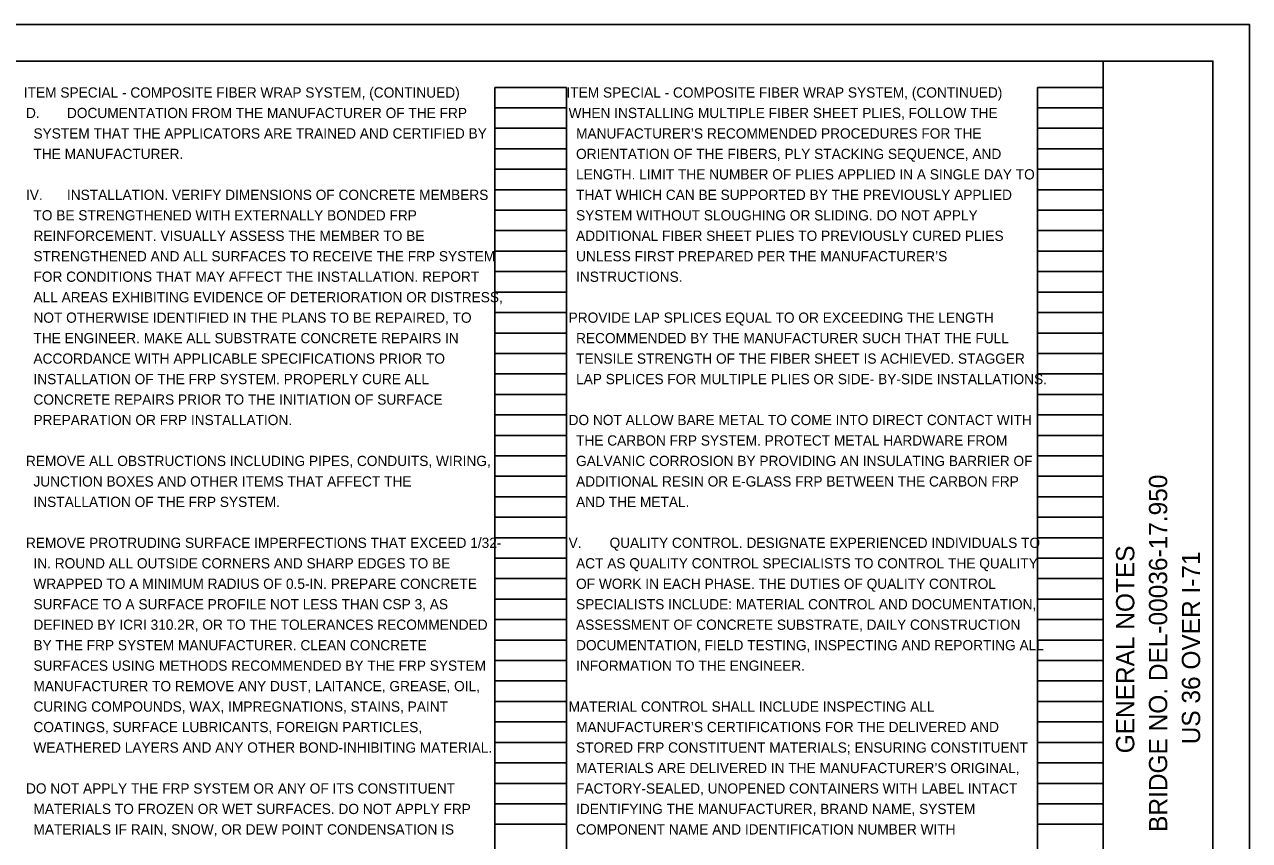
# Model space of a CAD drawing. Extents: x 0 to 90.2, y -3.7 to 22.
# Drawn here: x 17.25 to 34, y 10.84 to 22 of the extents above; entities that cross this region are included whole.
import ezdxf

# ---------------------------------------------------------------- set-up
doc = ezdxf.new("R2010")
doc.units = 0
for name, color, linetype in [('Default', 7, 'Continuous'), ('SH_Border', 7, 'Continuous'), ('SH_Cut_Line', 7, 'Continuous'), ('SH_Data', 7, 'Continuous'), ('SH_Text', 7, 'Continuous')]:
    doc.layers.add(name, color=color, linetype=linetype)

msp = doc.modelspace()

# ---------------------------------------------------------------- linework, layer by layer
at = {"layer": 'SH_Border'}
msp.add_line((32, 0.5), (32, 21.5), dxfattribs=at)
msp.add_lwpolyline([(1.5, 21.5), (33.5, 21.5), (33.5, 0.5), (1.5, 0.5)], close=True, dxfattribs=at)
at = {"layer": 'SH_Cut_Line'}
msp.add_lwpolyline([(0, 0), (34, 0), (34, 22), (0, 22)], close=True, dxfattribs=at)
at = {"layer": 'SH_Data'}
for p, q in [((23.68, 0.98), (23.68, 21.14)), ((23.68, 21.14), (24.66, 21.14)), ((24.66, 0.98), (24.66, 21.14)), ((31.1, 0.98), (31.1, 21.14)), ((31.1, 21.14), (32, 21.14)), ((32, 0.98), (32, 21.14)), ((23.68, 20.86), (24.66, 20.86)), ((31.1, 20.86), (32, 20.86)), ((23.68, 20.58), (24.66, 20.58)), ((31.1, 20.58), (32, 20.58)), ((23.68, 20.3), (24.66, 20.3)), ((31.1, 20.3), (32, 20.3)), ((23.68, 20.02), (24.66, 20.02)), ((31.1, 20.02), (32, 20.02)), ((23.68, 19.74), (24.66, 19.74)), ((31.1, 19.74), (32, 19.74)), ((23.68, 19.46), (24.66, 19.46)), ((31.1, 19.46), (32, 19.46)), ((23.68, 19.18), (24.66, 19.18)), ((31.1, 19.18), (32, 19.18)), ((23.68, 18.9), (24.66, 18.9)), ((31.1, 18.9), (32, 18.9)), ((23.68, 18.62), (24.66, 18.62)), ((31.1, 18.62), (32, 18.62)), ((23.68, 18.34), (24.66, 18.34)), ((31.1, 18.34), (32, 18.34)), ((23.68, 18.06), (24.66, 18.06)), ((31.1, 18.06), (32, 18.06)), ((23.68, 17.78), (24.66, 17.78)), ((31.1, 17.78), (32, 17.78)), ((23.68, 17.5), (24.66, 17.5)), ((31.1, 17.5), (32, 17.5)), ((23.68, 17.22), (24.66, 17.22)), ((31.1, 17.22), (32, 17.22)), ((23.68, 16.94), (24.66, 16.94)), ((31.1, 16.94), (32, 16.94)), ((23.68, 16.66), (24.66, 16.66)), ((31.1, 16.66), (32, 16.66)), ((23.68, 16.38), (24.66, 16.38)), ((31.1, 16.38), (32, 16.38)), ((23.68, 16.1), (24.66, 16.1)), ((31.1, 16.1), (32, 16.1)), ((23.68, 15.82), (24.66, 15.82)), ((31.1, 15.82), (32, 15.82)), ((23.68, 15.54), (24.66, 15.54)), ((31.1, 15.54), (32, 15.54)), ((23.68, 15.26), (24.66, 15.26)), ((31.1, 15.26), (32, 15.26)), ((23.68, 14.98), (24.66, 14.98)), ((31.1, 14.98), (32, 14.98)), ((23.68, 14.7), (24.66, 14.7)), ((31.1, 14.7), (32, 14.7)), ((23.68, 14.42), (24.66, 14.42)), ((31.1, 14.42), (32, 14.42)), ((23.68, 14.14), (24.66, 14.14)), ((31.1, 14.14), (32, 14.14)), ((23.68, 13.86), (24.66, 13.86)), ((31.1, 13.86), (32, 13.86)), ((23.68, 13.58), (24.66, 13.58)), ((31.1, 13.58), (32, 13.58)), ((23.68, 13.3), (24.66, 13.3)), ((31.1, 13.3), (32, 13.3)), ((23.68, 13.02), (24.66, 13.02)), ((31.1, 13.02), (32, 13.02)), ((23.68, 12.74), (24.66, 12.74)), ((31.1, 12.74), (32, 12.74)), ((23.68, 12.46), (24.66, 12.46)), ((31.1, 12.46), (32, 12.46)), ((23.68, 12.18), (24.66, 12.18)), ((31.1, 12.18), (32, 12.18)), ((23.68, 11.9), (24.66, 11.9)), ((31.1, 11.9), (32, 11.9)), ((23.68, 11.62), (24.66, 11.62)), ((31.1, 11.62), (32, 11.62)), ((23.68, 11.34), (24.66, 11.34)), ((31.1, 11.34), (32, 11.34)), ((23.68, 11.06), (24.66, 11.06)), ((31.1, 11.06), (32, 11.06))]:
    msp.add_line(p, q, dxfattribs=at)

# ---------------------------------------------------------------- texts
at = {"layer": 'Default'}
for s, p in [('D.', (17.269, 20.72)), ('DOCUMENTATION FROM THE MANUFACTURER OF THE FRP ', (17.829, 20.72)), ('WHEN INSTALLING MULTIPLE FIBER SHEET PLIES, FOLLOW THE ', (24.689, 20.72)), ('SYSTEM THAT THE APPLICATORS ARE TRAINED AND CERTIFIED BY ', (17.371, 20.44)), ('MANUFACTURER’S RECOMMENDED PROCEDURES FOR THE ', (24.791, 20.44)), ('THE MANUFACTURER.', (17.371, 20.16)), ('ORIENTATION OF THE FIBERS, PLY STACKING SEQUENCE, AND ', (24.791, 20.16)), ('LENGTH. LIMIT THE NUMBER OF PLIES APPLIED IN A SINGLE DAY TO ', (24.791, 19.88)), ('IV.', (17.269, 19.6)), ('INSTALLATION. VERIFY DIMENSIONS OF CONCRETE MEMBERS ', (17.829, 19.6)), ('THAT WHICH CAN BE SUPPORTED BY THE PREVIOUSLY APPLIED ', (24.791, 19.6)), ('TO BE STRENGTHENED WITH EXTERNALLY BONDED FRP ', (17.371, 19.32)), ('SYSTEM WITHOUT SLOUGHING OR SLIDING. DO NOT APPLY ', (24.791, 19.32)), ('REINFORCEMENT. VISUALLY ASSESS THE MEMBER TO BE ', (17.371, 19.04)), ('ADDITIONAL FIBER SHEET PLIES TO PREVIOUSLY CURED PLIES ', (24.791, 19.04)), ('STRENGTHENED AND ALL SURFACES TO RECEIVE THE FRP SYSTEM ', (17.371, 18.76)), ('UNLESS FIRST PREPARED PER THE MANUFACTURER’S ', (24.791, 18.76)), ('FOR CONDITIONS THAT MAY AFFECT THE INSTALLATION. REPORT ', (17.371, 18.48)), ('INSTRUCTIONS.', (24.791, 18.48)), ('ALL AREAS EXHIBITING EVIDENCE OF DETERIORATION OR DISTRESS, ', (17.371, 18.2)), ('NOT OTHERWISE IDENTIFIED IN THE PLANS TO BE REPAIRED, TO ', (17.371, 17.92)), ('PROVIDE LAP SPLICES EQUAL TO OR EXCEEDING THE LENGTH ', (24.689, 17.92)), ('THE ENGINEER. MAKE ALL SUBSTRATE CONCRETE REPAIRS IN ', (17.371, 17.64)), ('RECOMMENDED BY THE MANUFACTURER SUCH THAT THE FULL ', (24.791, 17.64)), ('ACCORDANCE WITH APPLICABLE SPECIFICATIONS PRIOR TO ', (17.371, 17.36)), ('TENSILE STRENGTH OF THE FIBER SHEET IS ACHIEVED. STAGGER ', (24.791, 17.36)), ('INSTALLATION OF THE FRP SYSTEM. PROPERLY CURE ALL ', (17.371, 17.08)), ('LAP SPLICES FOR MULTIPLE PLIES OR SIDE- BY-SIDE INSTALLATIONS.', (24.791, 17.08)), ('CONCRETE REPAIRS PRIOR TO THE INITIATION OF SURFACE ', (17.371, 16.8)), ('PREPARATION OR FRP INSTALLATION.', (17.371, 16.52)), ('DO NOT ALLOW BARE METAL TO COME INTO DIRECT CONTACT WITH ', (24.689, 16.52)), ('THE CARBON FRP SYSTEM. PROTECT METAL HARDWARE FROM ', (24.791, 16.24)), ('REMOVE ALL OBSTRUCTIONS INCLUDING PIPES, CONDUITS, WIRING, ', (17.269, 15.96)), ('GALVANIC CORROSION BY PROVIDING AN INSULATING BARRIER OF ', (24.791, 15.96)), ('JUNCTION BOXES AND OTHER ITEMS THAT AFFECT THE ', (17.371, 15.68)), ('ADDITIONAL RESIN OR E-GLASS FRP BETWEEN THE CARBON FRP ', (24.791, 15.68)), ('INSTALLATION OF THE FRP SYSTEM.', (17.371, 15.4)), ('AND THE METAL.', (24.791, 15.4)), ('REMOVE PROTRUDING SURFACE IMPERFECTIONS THAT EXCEED 1/32-', (17.269, 14.84)), ('V.', (24.689, 14.84)), ('QUALITY CONTROL. DESIGNATE EXPERIENCED INDIVIDUALS TO ', (25.249, 14.84)), ('IN. ROUND ALL OUTSIDE CORNERS AND SHARP EDGES TO BE ', (17.371, 14.56)), ('ACT AS QUALITY CONTROL SPECIALISTS TO CONTROL THE QUALITY ', (24.791, 14.56)), ('WRAPPED TO A MINIMUM RADIUS OF 0.5-IN. PREPARE CONCRETE ', (17.371, 14.28)), ('OF WORK IN EACH PHASE. THE DUTIES OF QUALITY CONTROL ', (24.791, 14.28)), ('SURFACE TO A SURFACE PROFILE NOT LESS THAN CSP 3, AS ', (17.371, 14)), ('SPECIALISTS INCLUDE: MATERIAL CONTROL AND DOCUMENTATION, ', (24.791, 14)), ('DEFINED BY ICRI 310.2R, OR TO THE TOLERANCES RECOMMENDED ', (17.371, 13.72)), ('ASSESSMENT OF CONCRETE SUBSTRATE, DAILY CONSTRUCTION ', (24.791, 13.72)), ('BY THE FRP SYSTEM MANUFACTURER. CLEAN CONCRETE ', (17.371, 13.44)), ('DOCUMENTATION, FIELD TESTING, INSPECTING AND REPORTING ALL ', (24.791, 13.44)), ('SURFACES USING METHODS RECOMMENDED BY THE FRP SYSTEM ', (17.371, 13.16)), ('INFORMATION TO THE ENGINEER.', (24.791, 13.16)), ('MANUFACTURER TO REMOVE ANY DUST, LAITANCE, GREASE, OIL, ', (17.371, 12.88)), ('CURING COMPOUNDS, WAX, IMPREGNATIONS, STAINS, PAINT ', (17.371, 12.6)), ('MATERIAL CONTROL SHALL INCLUDE INSPECTING ALL ', (24.689, 12.6)), ('COATINGS, SURFACE LUBRICANTS, FOREIGN PARTICLES, ', (17.371, 12.32)), ('MANUFACTURER’S CERTIFICATIONS FOR THE DELIVERED AND ', (24.791, 12.32)), ('WEATHERED LAYERS AND ANY OTHER BOND-INHIBITING MATERIAL.', (17.371, 12.04)), ('STORED FRP CONSTITUENT MATERIALS; ENSURING CONSTITUENT ', (24.791, 12.04)), ('MATERIALS ARE DELIVERED IN THE MANUFACTURER’S ORIGINAL, ', (24.791, 11.76)), ('DO NOT APPLY THE FRP SYSTEM OR ANY OF ITS CONSTITUENT ', (17.269, 11.48)), ('FACTORY-SEALED, UNOPENED CONTAINERS WITH LABEL INTACT ', (24.791, 11.48)), ('MATERIALS TO FROZEN OR WET SURFACES. DO NOT APPLY FRP ', (17.371, 11.2)), ('IDENTIFYING THE MANUFACTURER, BRAND NAME, SYSTEM ', (24.791, 11.2)), ('MATERIALS IF RAIN, SNOW, OR DEW POINT CONDENSATION IS ', (17.371, 10.92)), ('COMPONENT NAME AND IDENTIFICATION NUMBER WITH ', (24.791, 10.92))]:
    msp.add_text(s, height=0.14, dxfattribs=at).set_placement(p)
at = {"layer": 'SH_Data'}
for s, p in [('BRIDGE NO. DEL-00036-17.950', (32.875, 10.956)), ('GENERAL NOTES', (32.425, 12.031)), ('US 36 OVER I-71', (33.325, 12.154))]:
    msp.add_text(s, height=0.25, rotation=90, dxfattribs=at).set_placement(p)
at = {"layer": 'SH_Text'}
for p in [(17.24, 21), (24.66, 21)]:
    msp.add_text('ITEM SPECIAL - COMPOSITE FIBER WRAP SYSTEM, (CONTINUED)', height=0.14, dxfattribs=at).set_placement(p)

doc.saveas('drawing.dxf')
